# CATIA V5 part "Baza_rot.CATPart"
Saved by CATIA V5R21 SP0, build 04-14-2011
Part number: Baza_rot
Bounding box of the stored display mesh (mm): x -62.5 to 62.5, y -145 to -95, z -62.5 to 62.5
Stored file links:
  C:\Users\MIRCEA\Desktop\PRRO\CATIAV5\Baza_rot.CATPart
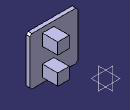
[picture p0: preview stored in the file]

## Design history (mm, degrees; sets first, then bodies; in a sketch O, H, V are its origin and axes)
Body1 (main body)
  Plane1: type Offset, RefPlane zx-plane, Offset -95
  Sketch1 on Plane1, origin (0, -95, 0), H (-1, 0, 0), V (0, 0, 1)
    line L1 (0, 20) -> (-30, 20)
    line L2 (-30, 20) -> (-30, 50)
    line L3 (-30, 50) -> (0, 50)
    line L4 (0, 50) -> (0, 20)
    line L5 (0, -20) -> (-30, -20)
    line L6 (-30, -20) -> (-30, -50)
    line L7 (-30, -50) -> (0, -50)
    line L8 (0, -50) -> (0, -20)
    distance L1 L3 = 30
    distance L2 L4 = 30
    distance L5 L7 = 30
    distance L6 L8 = 30
    horizontal: L1 H, L3 H, L5 H, L7 H
    vertical: L2 V, L4 V, L6 V, L8 V
  Pad1: profile Sketch1, direction (0, -1, 0), length 40
  Plane2: type Offset, RefPlane Plane1, Offset -40
  Sketch2 on Plane2, origin (0, -135, 0), H (-1, 0, 0), V (0, 0, 1)
    line L1 (62.5, 62.5) -> (62.5, -62.5)
    line L2 (62.5, -62.5) -> (-62.5, -62.5)
    line L3 (-62.5, -62.5) -> (-62.5, 62.5)
    line L4 (-62.5, 62.5) -> (62.5, 62.5)
    distance L2 L4 = 125
    distance L1 L3 = 125
    vertical: L1 V, L3 V
    horizontal: L2 H, L4 H
    equidistance: L1 L3 O, L2 L4 O
  Pad2: profile Sketch2, direction (0, -1, 0), length 10
  Chamfer1: length 5, angle 45, on edge [face of Pad2 from Sketch2.L4 | face of Pad2 from Sketch2.L3]; edge [face of Pad2 from Sketch2.L3 | face of Pad2 from Sketch2.L2]; edge [face of Pad2 from Sketch2.L2 | face of Pad2 from Sketch2.L1]; edge [face of Pad2 from Sketch2.L1 | face of Pad2 from Sketch2.L4]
